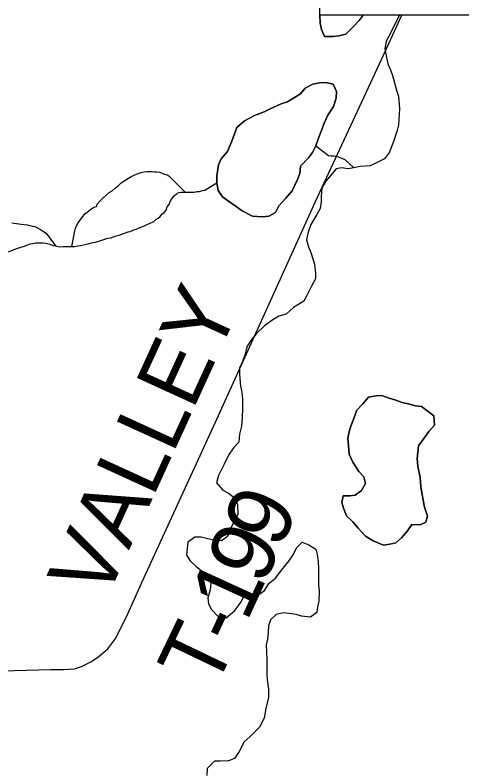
# Model space of a CAD drawing. Extents: x 0 to 34, y 0 to 22.
# Drawn here: x 3.448 to 3.842, y 16.919 to 17.584 of the extents above; entities that cross this region are included whole.
import ezdxf

# ---------------------------------------------------------------- set-up
doc = ezdxf.new("R2010")
doc.units = 0
for name, color, linetype in [('GM_X_Major_Lake', 7, 'Continuous'), ('GM_X_Major_River', 7, 'Continuous'), ('GM_X_Minor_Lake', 7, 'Continuous'), ('GM_X_Minor_River', 7, 'Continuous'), ('GM_X_Township_Road', 7, 'Continuous'), ('GM_X_Township_Road_Text', 7, 'Continuous'), ('SH_Border', 7, 'Continuous')]:
    doc.layers.add(name, color=color, linetype=linetype)

msp = doc.modelspace()

# ---------------------------------------------------------------- linework, layer by layer
at = {"layer": 'GM_X_Major_Lake'}
for points in [[(3.78697, 17.58349), (3.78315, 17.57635), (3.77859, 17.56723), (3.77517, 17.56077), (3.77404, 17.55393), (3.77517, 17.54785), (3.77669, 17.54064), (3.77896, 17.53532), (3.78086, 17.53038), (3.78427, 17.51747), (3.78616, 17.51215), (3.78692, 17.50114), (3.78616, 17.48708), (3.78464, 17.481), (3.78198, 17.47302), (3.77819, 17.46276), (3.77363, 17.45706), (3.76604, 17.45325), (3.76111, 17.45096), (3.75238, 17.45019), (3.74669, 17.44905), (3.74138, 17.44828), (3.73607, 17.44903), (3.73114, 17.44827), (3.72203, 17.43724), (3.71861, 17.43154), (3.71785, 17.42394), (3.71785, 17.419), (3.71709, 17.4133), (3.71405, 17.40798), (3.70874, 17.39924), (3.70608, 17.39164), (3.70494, 17.38556), (3.70684, 17.37948), (3.70873, 17.37455), (3.71214, 17.36429)], [(3.71214, 17.36429), (3.7129, 17.35632), (3.7129, 17.35138), (3.70948, 17.34492), (3.70531, 17.33655), (3.70265, 17.33161), (3.69354, 17.3259), (3.68709, 17.3202), (3.68064, 17.31829), (3.67457, 17.31448), (3.66812, 17.30992), (3.66091, 17.30307), (3.65597, 17.29699), (3.65256, 17.29128), (3.65104, 17.28483), (3.64876, 17.27836), (3.6461, 17.27266), (3.6461, 17.26697), (3.64686, 17.25671), (3.648, 17.25139), (3.64875, 17.24494), (3.64875, 17.23696), (3.64837, 17.22898), (3.64761, 17.22138), (3.64609, 17.21454), (3.64533, 17.20732), (3.64077, 17.20238), (3.63622, 17.19592), (3.63243, 17.18793), (3.62749, 17.17805), (3.62559, 17.17159), (3.63128, 17.16514), (3.63621, 17.16249), (3.64114, 17.15869), (3.64418, 17.15262), (3.64455, 17.1435), (3.64114, 17.1378), (3.63886, 17.13286), (3.63544, 17.12412), (3.63013, 17.12031), (3.62482, 17.12069), (3.61799, 17.1222), (3.6123, 17.12371), (3.60661, 17.1237), (3.60054, 17.11914), (3.5994, 17.10774), (3.60243, 17.10281), (3.60774, 17.09787), (3.61343, 17.09332), (3.61836, 17.08801), (3.62064, 17.08307), (3.62026, 17.07738), (3.61798, 17.07015), (3.61873, 17.06484), (3.62139, 17.0599), (3.62708, 17.05383), (3.63429, 17.0527), (3.64188, 17.05917), (3.64757, 17.06677), (3.65137, 17.07475), (3.65668, 17.074), (3.66313, 17.07324), (3.66806, 17.07667), (3.67224, 17.08313), (3.67793, 17.0877), (3.68286, 17.09454), (3.68931, 17.10253), (3.69311, 17.10823), (3.69615, 17.11431), (3.70108, 17.11925), (3.70715, 17.11698), (3.71322, 17.11319), (3.71436, 17.10825), (3.71512, 17.1018), (3.71549, 17.0961), (3.71549, 17.08128), (3.71625, 17.07635), (3.71587, 17.06723), (3.71473, 17.06229), (3.71397, 17.05735), (3.70865, 17.05316), (3.70069, 17.05391), (3.69575, 17.05543), (3.68513, 17.05694), (3.6783, 17.05541), (3.67337, 17.05084), (3.67147, 17.04552), (3.67109, 17.03982), (3.67071, 17.03375), (3.66957, 17.02881), (3.66994, 17.01589), (3.66994, 17.00335), (3.67032, 16.99804), (3.67145, 16.98968), (3.67145, 16.98246), (3.66917, 16.97258), (3.66766, 16.96422), (3.66348, 16.95624), (3.65551, 16.94788), (3.65019, 16.94331), (3.64564, 16.93495)], [(3.73714, 17.15994), (3.736, 17.15424), (3.73751, 17.14931), (3.74016, 17.14247), (3.74586, 17.13716), (3.75041, 17.13147), (3.75685, 17.12464), (3.76368, 17.12047), (3.77279, 17.11668), (3.77848, 17.11745), (3.78379, 17.11859), (3.78873, 17.12316), (3.79404, 17.12924), (3.79784, 17.13494), (3.80504, 17.13457), (3.80998, 17.13686), (3.81149, 17.14218), (3.80884, 17.15015), (3.8077, 17.15623), (3.80657, 17.16268), (3.80581, 17.16838), (3.80505, 17.17636), (3.80316, 17.18623), (3.8024, 17.19307), (3.80354, 17.20409), (3.80848, 17.21055), (3.81265, 17.21664), (3.81759, 17.22234), (3.81721, 17.2307), (3.81228, 17.23449), (3.80621, 17.23866), (3.8009, 17.23942), (3.79559, 17.24093), (3.78913, 17.24244), (3.78382, 17.24433), (3.77775, 17.24623), (3.7713, 17.2485), (3.76637, 17.24811), (3.75954, 17.24696), (3.75461, 17.24126), (3.7493, 17.23556), (3.74702, 17.22909), (3.74398, 17.22149), (3.74246, 17.21655), (3.74132, 17.21085), (3.74208, 17.2044), (3.74246, 17.1968), (3.74587, 17.18959), (3.75118, 17.18161), (3.75535, 17.17668), (3.75687, 17.17098), (3.75345, 17.1649), (3.74776, 17.16072), (3.7432, 17.15995)], [(3.7432, 17.15995), (3.73714, 17.15994)], [(3.64564, 16.93495), (3.64147, 16.92849), (3.63615, 16.92658), (3.62894, 16.92619), (3.62401, 16.92618), (3.61756, 16.91972), (3.61718, 16.91364)]]:
    msp.add_lwpolyline(points, dxfattribs=at)
at = {"layer": 'GM_X_Major_River'}
for points in [[(3.78697, 17.58349), (3.78315, 17.57635), (3.77859, 17.56723), (3.77517, 17.56077), (3.77404, 17.55393), (3.77517, 17.54785), (3.77669, 17.54064), (3.77896, 17.53532), (3.78086, 17.53038), (3.78427, 17.51747), (3.78616, 17.51215), (3.78692, 17.50114), (3.78616, 17.48708), (3.78464, 17.481), (3.78198, 17.47302), (3.77819, 17.46276), (3.77363, 17.45706), (3.76604, 17.45325), (3.76111, 17.45096), (3.75238, 17.45019), (3.74669, 17.44905), (3.74138, 17.44828), (3.73607, 17.44903), (3.73114, 17.44827), (3.72203, 17.43724), (3.71861, 17.43154), (3.71785, 17.42394), (3.71785, 17.419), (3.71709, 17.4133), (3.71405, 17.40798), (3.70874, 17.39924), (3.70608, 17.39164), (3.70494, 17.38556), (3.70684, 17.37948), (3.70873, 17.37455), (3.71214, 17.36429)], [(3.71214, 17.36429), (3.7129, 17.35632), (3.7129, 17.35138), (3.70948, 17.34492), (3.70531, 17.33655), (3.70265, 17.33161), (3.69354, 17.3259), (3.68709, 17.3202), (3.68064, 17.31829), (3.67457, 17.31448), (3.66812, 17.30992), (3.66091, 17.30307), (3.65597, 17.29699), (3.65256, 17.29128), (3.65104, 17.28483), (3.64876, 17.27836), (3.6461, 17.27266), (3.6461, 17.26697), (3.64686, 17.25671), (3.648, 17.25139), (3.64875, 17.24494), (3.64875, 17.23696), (3.64837, 17.22898), (3.64761, 17.22138), (3.64609, 17.21454), (3.64533, 17.20732), (3.64077, 17.20238), (3.63622, 17.19592), (3.63243, 17.18793), (3.62749, 17.17805), (3.62559, 17.17159), (3.63128, 17.16514), (3.63621, 17.16249), (3.64114, 17.15869), (3.64418, 17.15262), (3.64455, 17.1435), (3.64114, 17.1378), (3.63886, 17.13286), (3.63544, 17.12412), (3.63013, 17.12031), (3.62482, 17.12069), (3.61799, 17.1222), (3.6123, 17.12371), (3.60661, 17.1237), (3.60054, 17.11914), (3.5994, 17.10774), (3.60243, 17.10281), (3.60774, 17.09787), (3.61343, 17.09332), (3.61836, 17.08801), (3.62064, 17.08307), (3.62026, 17.07738), (3.61798, 17.07015), (3.61873, 17.06484), (3.62139, 17.0599), (3.62708, 17.05383), (3.63429, 17.0527), (3.64188, 17.05917), (3.64757, 17.06677), (3.65137, 17.07475), (3.65668, 17.074), (3.66313, 17.07324), (3.66806, 17.07667), (3.67224, 17.08313), (3.67793, 17.0877), (3.68286, 17.09454), (3.68931, 17.10253), (3.69311, 17.10823), (3.69615, 17.11431), (3.70108, 17.11925), (3.70715, 17.11698), (3.71322, 17.11319), (3.71436, 17.10825), (3.71512, 17.1018), (3.71549, 17.0961), (3.71549, 17.08128), (3.71625, 17.07635), (3.71587, 17.06723), (3.71473, 17.06229), (3.71397, 17.05735), (3.70865, 17.05316), (3.70069, 17.05391), (3.69575, 17.05543), (3.68513, 17.05694), (3.6783, 17.05541), (3.67337, 17.05084), (3.67147, 17.04552), (3.67109, 17.03982), (3.67071, 17.03375), (3.66957, 17.02881), (3.66994, 17.01589), (3.66994, 17.00335), (3.67032, 16.99804), (3.67145, 16.98968), (3.67145, 16.98246), (3.66917, 16.97258), (3.66766, 16.96422), (3.66348, 16.95624), (3.65551, 16.94788), (3.65019, 16.94331), (3.64564, 16.93495)], [(3.7432, 17.15995), (3.74776, 17.16072), (3.75345, 17.1649), (3.75687, 17.17098), (3.75535, 17.17668), (3.75118, 17.18161), (3.74587, 17.18959), (3.74246, 17.1968), (3.74208, 17.2044), (3.74132, 17.21085), (3.74246, 17.21655), (3.74398, 17.22149), (3.74702, 17.22909), (3.7493, 17.23556), (3.75461, 17.24126), (3.75954, 17.24696), (3.76637, 17.24811), (3.7713, 17.2485), (3.77775, 17.24623), (3.78382, 17.24433), (3.78913, 17.24244), (3.79559, 17.24093), (3.8009, 17.23942), (3.80621, 17.23866), (3.81228, 17.23449), (3.81721, 17.2307), (3.81759, 17.22234), (3.81265, 17.21664), (3.80848, 17.21055), (3.80354, 17.20409), (3.8024, 17.19307), (3.80316, 17.18623), (3.80505, 17.17636), (3.80581, 17.16838), (3.80657, 17.16268), (3.8077, 17.15623), (3.80884, 17.15015), (3.81149, 17.14218), (3.80998, 17.13686), (3.80504, 17.13457), (3.79784, 17.13494), (3.79404, 17.12924), (3.78873, 17.12316), (3.78379, 17.11859), (3.77848, 17.11745), (3.77279, 17.11668), (3.76368, 17.12047), (3.75685, 17.12464), (3.75041, 17.13147), (3.74586, 17.13716), (3.74016, 17.14247), (3.73751, 17.14931), (3.736, 17.15424), (3.73714, 17.15994)], [(3.73714, 17.15994), (3.7432, 17.15995)], [(3.64564, 16.93495), (3.64147, 16.92849), (3.63615, 16.92658), (3.62894, 16.92619), (3.62401, 16.92618), (3.61756, 16.91972), (3.61718, 16.91364)]]:
    msp.add_lwpolyline(points, dxfattribs=at)
at = {"layer": 'GM_X_Minor_Lake'}
for points in [[(3.75482, 17.58349), (3.75128, 17.57897), (3.74596, 17.57327), (3.73951, 17.5668), (3.73344, 17.56528), (3.72851, 17.56489), (3.72092, 17.56488), (3.71827, 17.57096), (3.71713, 17.57666), (3.71675, 17.58349)], [(3.71675, 17.58349), (3.71713, 17.57666), (3.71827, 17.57096), (3.72092, 17.56488), (3.72851, 17.56489), (3.73344, 17.56528), (3.73951, 17.5668), (3.74596, 17.57327), (3.75128, 17.57897), (3.75482, 17.58349)], [(3.70685, 17.45774), (3.69965, 17.45051), (3.69926, 17.44405), (3.69699, 17.43873), (3.69243, 17.42885), (3.68636, 17.42201), (3.68066, 17.41554), (3.67763, 17.40984), (3.67194, 17.40641), (3.66587, 17.40603), (3.65752, 17.4064), (3.64841, 17.41132), (3.6431, 17.41512), (3.63628, 17.41967), (3.63096, 17.42346), (3.62717, 17.42916), (3.62604, 17.43599), (3.62604, 17.44207), (3.62756, 17.45157), (3.62984, 17.45689), (3.63553, 17.46335), (3.63932, 17.47248), (3.6416, 17.47894), (3.6435, 17.48464), (3.65033, 17.49034), (3.65906, 17.49529), (3.66779, 17.49834), (3.6731, 17.50101), (3.68259, 17.50558), (3.68828, 17.5071), (3.69435, 17.51091), (3.69966, 17.51433), (3.70384, 17.51928), (3.71066, 17.5227), (3.71636, 17.52385), (3.72205, 17.52424), (3.7285, 17.52272), (3.73153, 17.51627), (3.73115, 17.51057), (3.72887, 17.50297), (3.72356, 17.49499), (3.72052, 17.48853), (3.71824, 17.48207), (3.71597, 17.47598), (3.71331, 17.46838), (3.71027, 17.46268), (3.70685, 17.45774)], [(3.70685, 17.45774), (3.71027, 17.46268), (3.71331, 17.46838), (3.71597, 17.47598), (3.71824, 17.48207), (3.72052, 17.48853), (3.72356, 17.49499), (3.72887, 17.50297), (3.73115, 17.51057), (3.73153, 17.51627), (3.7285, 17.52272), (3.72205, 17.52424), (3.71636, 17.52385), (3.71066, 17.5227), (3.70384, 17.51928), (3.69966, 17.51433), (3.69435, 17.51091), (3.68828, 17.5071), (3.68259, 17.50558), (3.6731, 17.50101), (3.66779, 17.49834), (3.65906, 17.49529), (3.65033, 17.49034), (3.6435, 17.48464)], [(3.6435, 17.48464), (3.6416, 17.47894), (3.63932, 17.47248), (3.63553, 17.46335), (3.62984, 17.45689), (3.62756, 17.45157), (3.62604, 17.44207), (3.62604, 17.43599), (3.62717, 17.42916), (3.63096, 17.42346), (3.63628, 17.41967), (3.6431, 17.41512), (3.64841, 17.41132), (3.65752, 17.4064), (3.66587, 17.40603), (3.67194, 17.40641), (3.67763, 17.40984), (3.68066, 17.41554), (3.68636, 17.42201), (3.69243, 17.42885), (3.69699, 17.43873), (3.69926, 17.44405), (3.69965, 17.45051), (3.70685, 17.45774)]]:
    msp.add_lwpolyline(points, dxfattribs=at)
at = {"layer": 'GM_X_Minor_River'}
for points in [[(3.71331, 17.46838), (3.72448, 17.45998), (3.72677, 17.45965), (3.72905, 17.4597), (3.73096, 17.45936), (3.73326, 17.45865), (3.73633, 17.45719), (3.73863, 17.45649), (3.74669, 17.44905)], [(3.49833, 17.37981), (3.50108, 17.39355), (3.50141, 17.39584), (3.50323, 17.39968), (3.50581, 17.40353), (3.50841, 17.40663), (3.50989, 17.40857), (3.51176, 17.41013), (3.51475, 17.41247), (3.51775, 17.41444), (3.52002, 17.41486), (3.52073, 17.41716), (3.52334, 17.41988), (3.52594, 17.4226), (3.52856, 17.42493), (3.53117, 17.42727), (3.5338, 17.42885), (3.53641, 17.43118), (3.53941, 17.43353), (3.54164, 17.43586), (3.54577, 17.43861), (3.55065, 17.44137), (3.55593, 17.44377), (3.55932, 17.44498), (3.56198, 17.44542), (3.56463, 17.44586), (3.56691, 17.44591), (3.56919, 17.44596), (3.5711, 17.44562), (3.573, 17.44566), (3.57567, 17.44534), (3.57952, 17.44352), (3.58219, 17.44282), (3.58373, 17.44209), (3.59811, 17.42759)], [(3.6061, 17.42776), (3.60837, 17.42819), (3.61065, 17.42824), (3.6133, 17.42905), (3.61557, 17.42949), (3.62604, 17.43599)], [(3.44251, 17.37517), (3.44892, 17.3776), (3.45345, 17.37921), (3.45648, 17.38004), (3.45874, 17.38085), (3.46176, 17.38206), (3.46403, 17.38248), (3.46631, 17.38292), (3.47049, 17.38301), (3.47315, 17.38306), (3.47544, 17.38273), (3.47888, 17.38167), (3.48157, 17.38059), (3.48386, 17.38025), (3.4873, 17.37957), (3.49072, 17.37964), (3.49338, 17.3797), (3.49566, 17.37975), (3.49833, 17.37981), (3.50061, 17.37986), (3.50326, 17.3803), (3.50591, 17.38073), (3.50857, 17.38117), (3.51273, 17.38202), (3.51576, 17.38285), (3.51916, 17.38368), (3.52219, 17.38451), (3.52484, 17.38533), (3.52748, 17.38614), (3.53013, 17.38696), (3.53278, 17.3874), (3.53505, 17.38821), (3.53731, 17.38902), (3.53996, 17.38984), (3.54222, 17.39065), (3.54788, 17.39267), (3.54978, 17.39309), (3.5528, 17.3943), (3.55506, 17.3951), (3.5577, 17.3963), (3.55996, 17.39711), (3.56223, 17.39792), (3.56448, 17.39911), (3.56675, 17.39992), (3.57051, 17.4019), (3.57238, 17.40346), (3.57426, 17.40464), (3.57612, 17.4062), (3.57761, 17.40814), (3.57948, 17.4097), (3.58134, 17.41164), (3.58241, 17.4147), (3.58389, 17.41663), (3.58498, 17.41932), (3.58645, 17.42163), (3.58829, 17.42433), (3.59054, 17.42628), (3.59241, 17.42746), (3.59469, 17.42751), (3.59811, 17.42759), (3.60268, 17.42768), (3.6061, 17.42776)], [(3.44538, 17.4007), (3.45378, 17.39936), (3.45645, 17.39904), (3.45912, 17.39872), (3.46141, 17.39839), (3.46333, 17.39767), (3.46562, 17.39734), (3.46754, 17.39662), (3.47062, 17.39479), (3.47254, 17.39369), (3.47563, 17.39148), (3.48386, 17.38025)]]:
    msp.add_lwpolyline(points, dxfattribs=at)
at = {"layer": 'GM_X_Township_Road'}
for points in [[(3.51497, 17.01385), (3.52088, 17.01763), (3.52986, 17.0252), (3.53696, 17.03466), (3.5476, 17.05617), (3.55989, 17.0836), (3.62444, 17.22452), (3.66511, 17.31366), (3.71287, 17.41935), (3.76938, 17.54065), (3.78895, 17.58349)], [(3.11354, 17.00208), (3.15791, 17.00306), (3.25062, 17.00392), (3.32461, 17.00477), (3.39131, 17.00558), (3.43724, 17.00592), (3.4795, 17.00699), (3.49117, 17.00712), (3.50078, 17.0077), (3.50693, 17.0096), (3.51497, 17.01385)]]:
    msp.add_lwpolyline(points, dxfattribs=at)
at = {"layer": 'SH_Border'}
msp.add_lwpolyline([(3.71675, 18.37642), (5.81986, 18.37642), (5.81986, 17.58349), (3.71675, 17.58349)], close=True, dxfattribs=at)

# ---------------------------------------------------------------- texts
at = {"layer": 'GM_X_Township_Road_Text'}
for s, height, rotation, p in [('VALLEY', 0.056818, 65.42844, (3.52745, 17.06566)), ('9', 0.05682, 65.53256, (3.68136, 17.1118)), ('9', 0.05682, 65.50692, (3.66684, 17.07992)), ('1', 0.05682, 65.41175, (3.65223, 17.048)), ('-', 0.05682, 65.21072, (3.64236, 17.02662)), ('T', 0.05682, 64.37413, (3.62359, 16.98748))]:
    msp.add_text(s, height=height, rotation=rotation, dxfattribs=at).set_placement(p)

doc.saveas('drawing.dxf')
